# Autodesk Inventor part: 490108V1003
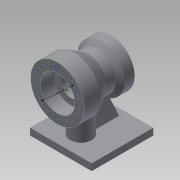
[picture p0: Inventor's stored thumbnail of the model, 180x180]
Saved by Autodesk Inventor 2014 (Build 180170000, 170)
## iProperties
Created: 2019-01
Part Number: 490108V1003
Material: 일반
Document SubType Name: Modeling
Designer: 601-05
Density: 1 g/cm^3
Appearance: 기본값
Author: 601-05
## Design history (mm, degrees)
sketch "스케치1"
  geometry: L1 (0, 0)-(0, 40); L2 (0, 40)-(25, 40); L3 (25, 40)-(45.785, 28); L4 (45.785, 28)-(59.126, 28); L5 (59.126, 28)-(65, 35); L6 (65, 35)-(80, 35); L7 (80, 35)-(80, 0); L8 (80, 0)-(0, 0)
  constraints: 16 end point, 4 parallel, 1 perpendicular, 1 vertical
  dimensions: "d9" = 30 deg angle of L4 L3; "d10" = 50 deg angle of L4 L5; "d11" = 80 diameter of L2 L8; "d12" = 70 diameter of L6 L8; "d13" = 25 distance of L1.end L2.end; "d14" = 15 distance of L5.end L6.end; "d16" = 56 diameter of L4 L8; "d17" = 80 distance of L7.end L1.start
revolve "회전1" sketch "스케치1" stored, may be unused: angle "d18" = 90 deg
sketch "스케치2"
  geometry: L1 (0, 0)-(0, 26); L2 (0, 26)-(19, 26); L3 (20, 25)-(20, 16); L4 (20, 16)-(63, 16); L5 (63, 16)-(63, 19.4); L6 (63.6, 20)-(80, 20); L7 (80, 20)-(80, 0); L8 (80, 0)-(0, 0); L9 (0, -40)-(0, 40) reference; L10 (80, -35)-(80, 35) reference; A1 r 1 centre (19, 25) between (20, 25) and (19, 26); A2 r 0.6 centre (63.6, 19.4) between (63.6, 20) and (63, 19.4)
  constraints: 16 end point, 6 parallel, 4 point on circle, 4 tangent, 2 centre point, 1 midpoint, 1 perpendicular, 1 vertical
  dimensions: "d19" = 20 distance between parallel lines of L3 L1; "d20" = 17 distance between parallel lines of L7 L5; "d21" = 52 diameter of L2 L8; "d22" = 32 diameter of L4 L8; "d23" = 40 diameter of L6 L8; "d24" = 1 radius of A1; "d25" = 0.6 radius of A2
revolve "회전2" sketch "스케치2" stored, may be unused: angle "d26" = 90 deg
node "작업 평면1"
node "작업축1"
  node "작업 평면2"
sketch "스케치3"
  geometry: L1 (0, 40)-(0, -40) reference; L2 (-5, 46)-(-97, 46); L3 (-97, 46)-(-97, -46); L4 (-97, -46)-(-5, -46); L5 (-5, -46)-(-5, 46); L6 (-5, 46)-(-97, -46); L7 (-97, 46)-(-5, -46); 3 further points
  constraints: 12 end point, 4 midpoint, 2 parallel, 1 horizontal, 1 horizontal alignment, 1 perpendicular
  dimensions: "d32" = 92 distance of L4.end L3.end; "d33" = 92 distance of L3.end L2.end; "d34" = 5 distance between parallel lines of L5 L1
extrude "돌출1" join sketch "스케치3" distance "d30" = 10; taper "d31" = 0 deg
sketch "스케치4"
  geometry: L1 (97, -46)-(97, 46) reference; L2 (97, 46)-(5, 46) reference; L3 (5, 46)-(5, -46) reference; L4 (50.199, 5)-(87, 5); L5 (87, 5)-(87, -5); L6 (87, -5)-(50.199, -5); L7 (51, -5)-(51, 5); L8 (97, -46)-(97, 46) reference; A1 r 16 centre (35, 0) between (51, 0) and (50.199, 5); 2 further points
  constraints: 8 end point, 3 point on circle, 2 horizontal alignment, 2 midpoint, 2 parallel, 2 point on line, 1 centre point, 1 horizontal, 1 perpendicular
  dimensions: "d36" = 16 radius of A1; "d37" = 10 distance between parallel lines of L6 L4; "d38" = 10 distance between parallel lines of L5 L1; "d39" = 46 distance from line of A1.centre L2 (derived); "d40" = 30 distance from line of A1.centre L3
extrude "돌출2" join sketch "스케치4" stored distance "d41" = 10; taper "d42" = 0 deg
extrude "돌출3" join sketch "스케치4" distance "d43" = 45; taper "d44" = 0 deg
feature "면 기울기1" dims angle "d45" = 25 deg
sketch "스케치5" dims "d46" = 66
  geometry: C1 r 26 at (0, 0) reference; C2 r 40 at (0, 0) reference; 2 further points
  constraints: 3 coincident, 2 vertical alignment, 2 other
node "솔리드1"
